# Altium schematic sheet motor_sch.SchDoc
size A4; PageSetup: Record=PageOptions¦CenterHorizontal=True¦CenterVertical=True¦PrintScale=1.00¦XCorrection=1.00¦YCorrection=1.00¦PrintKind=0¦BorderSize=5000000¦LeftOffset=0¦BottomOffset=0¦Orientation=2¦PaperLength=1000¦PaperWidth=1000¦Scale=100¦PaperSource=7¦PrintQuality=-3¦MediaType=1¦DitherType=10¦PrintScaleMode=1¦PaperKind=A4¦PaperIndex=9
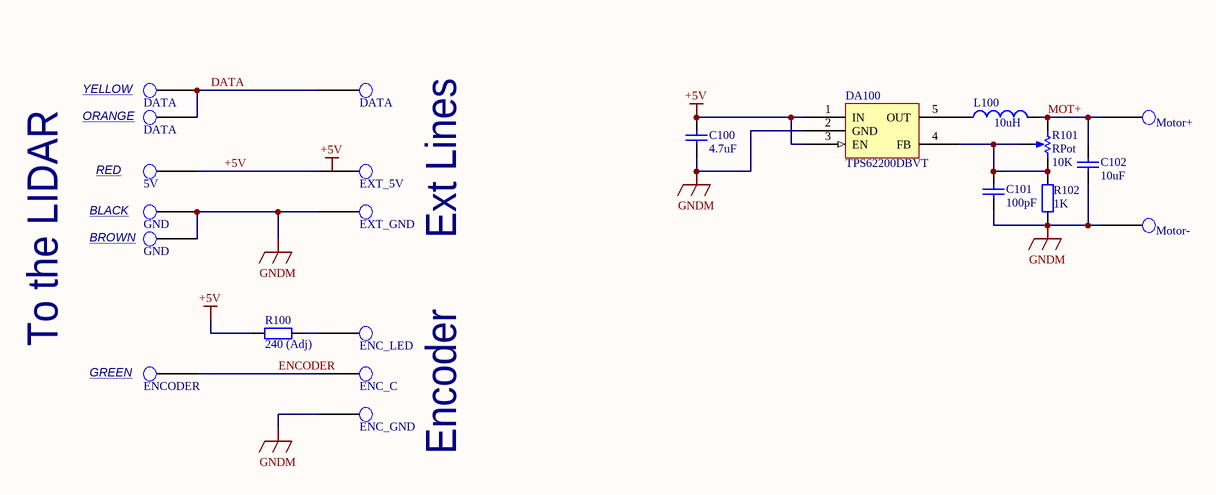
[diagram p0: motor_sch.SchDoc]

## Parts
C100  4.7uF  [CAPC2012X135N]
C101  100pF  [CAPC1608X90N]
C102  10uF  [CAPC3216X100N]
DA100  TPS62200DBVT  [SOT23-5]
L100  value 10uH  [INDC3216]  (hidden comment: Inductor)
P101  DATA  [Ext_pad]
P102  DATA  [Ext_pad]
P103  DATA  [Ext_pad]
P104  ENC_LED  [Ext_pad]
P105  ENC_C  [Ext_pad]
P106  ENC_GND  [Ext_pad]
P107  ENCODER  [Ext_pad]
P109  5V  [Ext_pad]
P110  EXT_5V  [Ext_pad]
P111  EXT_GND  [Ext_pad]
P112  Motor+  [Ext_hole]
P113  Motor-  [Ext_hole]
P114  GND  [Ext_pad]
P115  GND  [Ext_pad]
R100  240 (Adj)  [RESC1608X55N]
R101  RPot  value 10K  [VR5]
R102  1K  [RESC1608X55N]

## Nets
+5V: C100.2 DA100.1(IN) DA100.3(EN) P109.1(Pad) P110.1(Pad) R100.2
GNDM: C100.1 C101.1 C102.1 DA100.2(GND) P106.1(Pad) P111.1(Pad) P113.1(Pad) P114.1(Pad) P115.1(Pad) R102.1
DATA: P101.1(Pad) P102.1(Pad) P103.1(Pad)
ENCODER: P105.1(Pad) P107.1(Pad)
MOT+: C102.2 L100.2 P112.1(Pad) R101.1(TOP)
NetC101_2: C101.2 DA100.4(FB) R101.2(BOT) R101.3(TAP) R102.2
NetDA100_5: DA100.5(OUT) L100.1
NetP104_1: P104.1(Pad) R100.1

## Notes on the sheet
- YELLOW
- ORANGE
- RED
- BLACK
- BROWN
- Ext Lines
- To the LIDAR
- (near P107) GREEN
- Encoder
- Labels drawn without touching a wire or pin: +5V

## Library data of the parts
C100-C102 = CC0805: Chip capacitor; Voltage: 25V
DA100 = TPS62200: DC-DC step-down
L100 = Inductor: Code_IEC: 1005
P101-P107 P109-P111 P114 P115 = Ext Pad: Pad for wire
P112 P113 = Hole Pad
R100 R102 = RC0805: Chip resistor; Tolerance: 5%
R101 = RPot: Potentiometer; Sim Note: Enter the Resistance value and the set point into parameter fields.; Set Position: 0.5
